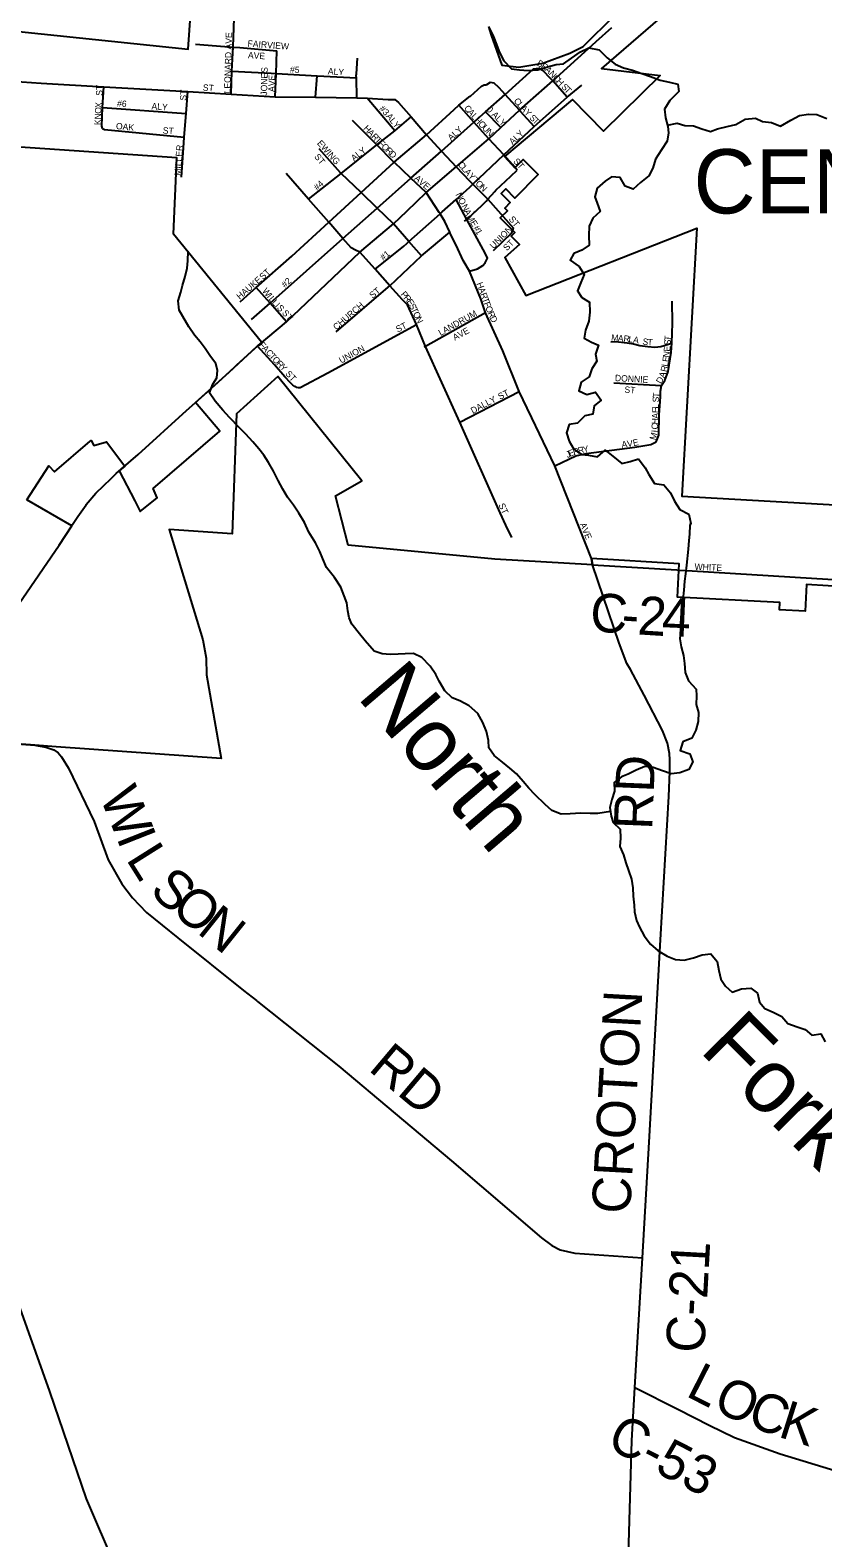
# Model space of a CAD drawing. Extents: x 1759416 to 2214760, y 252598 to 1116833.
# Drawn here: x 1910678 to 1916849, y 828969 to 840708 of the extents above; entities that cross this region are included whole.
import ezdxf

# ---------------------------------------------------------------- set-up
doc = ezdxf.new("R2010")
doc.units = 0
for name, color, linetype in [('GM_X_City_Street', 7, 'Continuous'), ('GM_X_City_Street_Text', 7, 'Continuous'), ('GM_X_Corporation', 7, 'Continuous'), ('GM_X_Corporation_Text', 7, 'Continuous'), ('GM_X_County_Road', 7, 'Continuous'), ('GM_X_County_Road_Text', 7, 'Continuous'), ('GM_X_Major_River', 7, 'Continuous'), ('GM_X_Major_River_Text', 7, 'Continuous'), ('GM_X_Minor_River', 7, 'Continuous'), ('GM_X_Township_Road', 7, 'Continuous'), ('GM_X_Township_Road_Text', 7, 'Continuous'), ('GM_X_US_Route', 7, 'Continuous')]:
    doc.layers.add(name, color=color, linetype=linetype)

msp = doc.modelspace()

# ---------------------------------------------------------------- linework, layer by layer
at = {"layer": 'GM_X_City_Street'}
for points in [[(1912257, 840579), (1912269, 840873), (1912279, 841107)], [(1911964, 840600), (1912257, 840576), (1912310, 840572)], [(1912242, 840210), (1912249, 840390), (1912257, 840576), (1912257, 840579)], [(1912310, 840572), (1912310, 840572), (1912599, 840548)], [(1912592, 840369), (1912592, 840371), (1912599, 840548)], [(1913218, 840367), (1913226, 840491)], [(1909520, 840374), (1909783, 840362), (1910763, 840296), (1911251, 840268), (1911905, 840230), (1912242, 840210), (1912585, 840190), (1912898, 840186), (1913222, 840182), (1913301, 840179), (1913465, 840169), (1913516, 840167), (1913546, 840146), (1913643, 840033), (1913762, 839892), (1913879, 839767), (1913993, 839645)], [(1912249, 840390), (1912555, 840373), (1912555, 840373)], [(1912400, 838454), (1912545, 838583), (1913111, 839086), (1913379, 839323), (1913642, 839556), (1913879, 839767), (1914132, 839992), (1914222, 840072), (1914375, 840208), (1914596, 840406), (1914637, 840412)], [(1912555, 840373), (1912592, 840371), (1912913, 840353), (1913218, 840336)], [(1912585, 840190), (1912592, 840369)], [(1914731, 840329), (1914670, 840393), (1914637, 840412)], [(1911241, 839942), (1911235, 839961), (1911242, 840105), (1911251, 840268)], [(1912898, 840186), (1912913, 840353)], [(1913222, 840182), (1913218, 840336), (1913217, 840356), (1913218, 840367)], [(1914103, 840193), (1914105, 840194), (1914192, 840273), (1914212, 840283), (1914230, 840282)], [(1914355, 840230), (1914326, 840261), (1914290, 840296), (1914259, 840300), (1914230, 840282)], [(1914859, 840187), (1914746, 840313), (1914731, 840329)], [(1914859, 840187), (1914973, 840279)], [(1911875, 839830), (1911878, 839876), (1911892, 840060), (1911905, 840230)], [(1913517, 839924), (1913301, 840179)], [(1913979, 840091), (1914014, 840123), (1914103, 840193)], [(1914121, 839506), (1914124, 839508), (1914366, 839736), (1914601, 839957), (1914859, 840187)], [(1914496, 840075), (1914486, 840086), (1914375, 840208), (1914355, 840230)], [(1911242, 840105), (1911892, 840060)], [(1912392, 838665), (1912437, 838705), (1912715, 838949), (1913002, 839212), (1913254, 839443), (1913512, 839679), (1913762, 839892), (1913979, 840091)], [(1912845, 839393), (1913098, 839593), (1913377, 839814), (1913517, 839924), (1913643, 840033)], [(1914470, 839619), (1914434, 839663), (1914366, 839736), (1914248, 839863), (1914132, 839992), (1914014, 840123)], [(1914341, 839950), (1914222, 840072)], [(1914601, 839957), (1914496, 840075)], [(1911241, 839942), (1911256, 839934), (1911878, 839876)], [(1913505, 839686), (1913377, 839814), (1913186, 840005)], [(1911855, 839563), (1911875, 839830), (1911875, 839830)], [(1913095, 839597), (1912927, 839783)], [(1913760, 839445), (1913642, 839556), (1913512, 839679), (1913505, 839686)], [(1913210, 838995), (1913176, 839012), (1913111, 839086), (1913002, 839212), (1912845, 839393), (1912671, 839593)], [(1913725, 838950), (1913626, 839063), (1913507, 839200), (1913379, 839323), (1913254, 839443), (1913098, 839593), (1913095, 839597)], [(1913993, 839645), (1914097, 839535)], [(1914304, 839461), (1914421, 839570), (1914470, 839619)], [(1913951, 839120), (1913944, 839134), (1913906, 839218), (1913869, 839279), (1913863, 839288), (1913760, 839445)], [(1913885, 839294), (1913993, 839390), (1914100, 839485), (1914121, 839506)], [(1914097, 839535), (1914105, 839527), (1914124, 839508), (1914205, 839429)], [(1914205, 839429), (1914242, 839393), (1914441, 839167)], [(1914227, 839376), (1914242, 839393), (1914296, 839453), (1914304, 839461)], [(1914098, 838831), (1914159, 838851), (1914203, 838876), (1914221, 838897), (1914239, 838934), (1914219, 838972), (1914076, 839235), (1913993, 839390)], [(1914144, 839297), (1914208, 839356), (1914227, 839376)], [(1913609, 839048), (1913626, 839063), (1913869, 839279), (1913885, 839294)], [(1914060, 839220), (1914076, 839235), (1914134, 839288), (1914144, 839297)], [(1913465, 838706), (1913478, 838717), (1913725, 838950), (1913944, 839134)], [(1914584, 837690), (1914548, 837765), (1914484, 837894), (1914358, 838211), (1914223, 838508), (1914185, 838617), (1914098, 838831), (1914050, 838914), (1913993, 839034), (1913951, 839120)], [(1914286, 838993), (1914427, 839131), (1914441, 839167)], [(1914011, 837684), (1913755, 838246), (1913686, 838417), (1913615, 838570), (1913577, 838608), (1913478, 838717), (1913363, 838848), (1913244, 838979), (1913210, 838995)], [(1913363, 838848), (1913586, 839027), (1913609, 839048)], [(1912312, 838594), (1912392, 838665)], [(1912673, 838437), (1912545, 838583), (1912437, 838705)], [(1913059, 838358), (1913465, 838706)], [(1914223, 838508), (1913755, 838246), (1913745, 838240)], [(1915593, 837941), (1915619, 837981), (1915645, 838050), (1915669, 838198), (1915672, 838270), (1915679, 838426), (1915675, 838598)], [(1912748, 837928), (1912765, 837925), (1912780, 837927), (1912994, 838040), (1913686, 838417)], [(1915197, 838282), (1915235, 838283), (1915325, 838274), (1915375, 838267), (1915424, 838252), (1915486, 838244), (1915542, 838240), (1915588, 838246), (1915672, 838270)], [(1912748, 837928), (1912737, 837933), (1912724, 837943), (1912705, 837963), (1912661, 838008), (1912580, 838102), (1912447, 838248)], [(1915221, 837962), (1915593, 837941)], [(1915550, 837504), (1915571, 837555), (1915575, 837714), (1915584, 837853), (1915585, 837896), (1915593, 837941)], [(1914023, 837657), (1914484, 837894)], [(1914338, 836951), (1914023, 837657), (1914011, 837684)], [(1915055, 836544), (1915048, 836595), (1914762, 837317), (1914584, 837690)], [(1914762, 837317), (1914925, 837393), (1915005, 837411), (1915385, 837460), (1915509, 837483), (1915550, 837504)], [(1914427, 836757), (1914381, 836854), (1914338, 836951)], [(1915731, 836504), (1915832, 836498), (1917226, 836412), (1917240, 836411)]]:
    msp.add_lwpolyline(points, dxfattribs=at)
at = {"layer": 'GM_X_Corporation'}
for points in [[(1910464, 840711), (1911908, 840559), (1912003, 841929)], [(1916038, 841202), (1915126, 840409), (1915581, 840356), (1915142, 839922), (1914899, 840169), (1914370, 839724), (1914452, 839635), (1914517, 839700), (1914633, 839583), (1914451, 839401), (1914380, 839472), (1914345, 839437), (1914415, 839366), (1914373, 839323), (1914394, 839302), (1914337, 839246), (1914450, 839132), (1914422, 839104), (1914487, 839039), (1914373, 838938), (1914536, 838641), (1915869, 839166), (1915751, 837079), (1917264, 836994)], [(1914246, 840737), (1914267, 840669), (1914350, 840436), (1914482, 840419), (1914669, 840451), (1914880, 840528), (1914982, 840580), (1915229, 840824)], [(1910652, 837052), (1910822, 837317), (1910867, 837270), (1911144, 837507), (1911153, 837512), (1911173, 837473), (1911273, 837504), (1911415, 837314), (1911372, 837277), (1911492, 837043), (1911533, 836961), (1911666, 837067), (1911635, 837139), (1912154, 837585), (1911965, 837808), (1912227, 838046), (1912479, 838278), (1911793, 839120), (1911820, 839713), (1910333, 839814)], [(1917228, 836362), (1916722, 836393), (1916712, 836184), (1916512, 836195), (1916515, 836252), (1915716, 836294), (1915730, 836554), (1915048, 836595), (1915055, 836544), (1914295, 836590), (1913153, 836697), (1913054, 837082), (1913261, 837198), (1912607, 838012), (1912284, 837720), (1912251, 836787), (1911759, 836821), (1912022, 835962), (1912047, 835818), (1912050, 835689), (1912164, 835037), (1910881, 835127), (1910714, 835140), (1910611, 835150)], [(1910621, 836286), (1910904, 836697), (1911001, 836848), (1910652, 837052)]]:
    msp.add_lwpolyline(points, dxfattribs=at)
at = {"layer": 'GM_X_County_Road'}
for points in [[(1915272, 828533), (1915299, 828607), (1915314, 828656), (1915319, 828724), (1915335, 828838), (1915361, 829727), (1915385, 830140), (1915419, 830710), (1915444, 831150), (1915496, 832049), (1915584, 833625), (1915649, 834741), (1915657, 834937), (1915658, 835027), (1915654, 835077), (1915639, 835157), (1915600, 835256), (1915457, 835530), (1915351, 835731), (1915323, 835777), (1915263, 835934), (1915055, 836544)], [(1915055, 836544), (1915713, 836505), (1915731, 836504)], [(1915385, 830140), (1915724, 829968), (1915965, 829847), (1916162, 829751), (1916516, 829624), (1916969, 829485), (1917203, 829435), (1917350, 829400), (1917440, 829373), (1917542, 829330), (1917705, 829256), (1918107, 829050), (1918465, 828869), (1918726, 828709), (1918986, 828539), (1919156, 828428), (1919288, 828347), (1919327, 828329), (1919359, 828320), (1919435, 828299)]]:
    msp.add_lwpolyline(points, dxfattribs=at)
at = {"layer": 'GM_X_Major_River'}
for points in [[(1914250, 840726), (1914285, 840655), (1914309, 840597), (1914331, 840535), (1914364, 840469), (1914424, 840408), (1914487, 840398), (1914555, 840393), (1914631, 840399), (1914705, 840423), (1914773, 840440), (1914829, 840446), (1914893, 840491), (1914962, 840539), (1915028, 840571), (1915108, 840556), (1915169, 840492), (1915231, 840443), (1915298, 840415), (1915368, 840396), (1915440, 840370), (1915508, 840347), (1915581, 840319), (1915655, 840304), (1915721, 840288), (1915727, 840230), (1915658, 840160), (1915616, 840093), (1915623, 840026), (1915641, 839958), (1915647, 839908), (1915636, 839844), (1915592, 839776), (1915545, 839703), (1915525, 839633), (1915493, 839575), (1915428, 839523), (1915372, 839470), (1915310, 839494), (1915271, 839562), (1915203, 839565), (1915153, 839531), (1915091, 839479), (1915074, 839411), (1915092, 839361), (1915115, 839295), (1915059, 839245), (1915029, 839181), (1915028, 839109), (1915030, 839035), (1914973, 838994), (1914909, 838970), (1914881, 838916), (1914953, 838868), (1914990, 838805), (1914966, 838743), (1914939, 838678), (1914973, 838627), (1915033, 838589), (1915036, 838513), (1915026, 838443), (1915001, 838373), (1914991, 838309), (1915049, 838279), (1915102, 838256), (1915080, 838186), (1915090, 838130), (1915051, 838072), (1915029, 838008), (1914967, 837967), (1914950, 837899), (1915012, 837872), (1915078, 837890), (1915123, 837828), (1915069, 837784), (1915059, 837718), (1914995, 837706), (1914939, 837649), (1914873, 837639), (1914854, 837573), (1914874, 837507), (1914909, 837445), (1914973, 837404), (1915025, 837398), (1915095, 837386), (1915155, 837437), (1915214, 837391), (1915284, 837334), (1915348, 837350), (1915414, 837370)], [(1915414, 837370), (1915466, 837301), (1915495, 837249), (1915539, 837179), (1915612, 837168), (1915664, 837106), (1915693, 837040), (1915735, 836977), (1915805, 836939), (1915822, 836867)], [(1915822, 836867), (1915812, 836853), (1915810, 836785), (1915805, 836735), (1915801, 836667), (1915788, 836543), (1915780, 836475), (1915773, 836417), (1915767, 836347), (1915758, 836275), (1915748, 836197), (1915743, 836134), (1915741, 836082), (1915741, 836032), (1915736, 835970), (1915746, 835906), (1915765, 835838), (1915773, 835776), (1915776, 835708), (1915802, 835642), (1915863, 835577), (1915865, 835525), (1915863, 835457), (1915880, 835395), (1915878, 835325), (1915861, 835257), (1915829, 835195), (1915759, 835166), (1915738, 835100), (1915812, 835073), (1915836, 835011), (1915805, 834951), (1915735, 834926), (1915667, 834918), (1915600, 834942), (1915528, 834967), (1915464, 834975), (1915396, 834946), (1915332, 834914), (1915280, 834894), (1915225, 834851), (1915227, 834783), (1915205, 834719), (1915190, 834655), (1915200, 834589), (1915217, 834539), (1915271, 834488), (1915273, 834418), (1915268, 834352), (1915298, 834288), (1915315, 834226), (1915337, 834164), (1915358, 834097), (1915370, 834031), (1915371, 833965), (1915379, 833895), (1915383, 833843), (1915398, 833775), (1915422, 833723), (1915457, 833656), (1915507, 833592), (1915566, 833540), (1915638, 833499), (1915702, 833473), (1915769, 833466), (1915841, 833484), (1915908, 833509), (1915977, 833517), (1916025, 833457), (1916040, 833387), (1916054, 833318), (1916090, 833264), (1916143, 833218), (1916215, 833243), (1916287, 833249), (1916339, 833209), (1916356, 833140), (1916398, 833090), (1916462, 833062), (1916529, 833029), (1916577, 832975), (1916649, 832948), (1916710, 832928), (1916764, 832882), (1916832, 832893), (1916868, 832831)]]:
    msp.add_lwpolyline(points, dxfattribs=at)
at = {"layer": 'GM_X_Minor_River'}
for points in [[(1915639, 839967), (1915715, 839983), (1915775, 839965), (1915843, 839963), (1915907, 839941), (1915975, 839919), (1916029, 839941), (1916103, 839957), (1916172, 839974), (1916244, 840014), (1916324, 840024), (1916378, 839996), (1916448, 839990), (1916520, 839960), (1916600, 840008), (1916668, 840044), (1916737, 840053), (1916803, 840051), (1916879, 840019)], [(1915195, 834624), (1915098, 834609), (1915038, 834609), (1914966, 834612), (1914882, 834606), (1914812, 834604), (1914739, 834632), (1914687, 834680), (1914607, 834757), (1914559, 834807), (1914516, 834859), (1914464, 834917), (1914412, 834963), (1914354, 835010), (1914291, 835060), (1914249, 835120), (1914245, 835178), (1914231, 835248), (1914203, 835318), (1914164, 835387), (1914096, 835447), (1914022, 835485), (1913962, 835509), (1913905, 835563), (1913861, 835640), (1913837, 835690), (1913793, 835756), (1913726, 835824), (1913662, 835854), (1913598, 835853), (1913542, 835849), (1913480, 835847), (1913419, 835851), (1913357, 835873), (1913285, 835953), (1913241, 836008), (1913182, 836082), (1913162, 836132), (1913152, 836186), (1913142, 836248), (1913122, 836304), (1913096, 836371), (1913047, 836447), (1912985, 836525), (1912957, 836591), (1912933, 836649), (1912900, 836716), (1912848, 836800), (1912814, 836876), (1912769, 836948), (1912727, 837010), (1912681, 837071), (1912645, 837135), (1912608, 837201), (1912572, 837275), (1912534, 837341), (1912496, 837398), (1912458, 837448), (1912411, 837502), (1912357, 837562), (1912307, 837612), (1912230, 837693), (1912178, 837749), (1912118, 837819), (1912074, 837883), (1912100, 837951), (1912130, 838002), (1912137, 838058), (1912123, 838112), (1912083, 838168), (1912041, 838230), (1912001, 838282), (1911956, 838332), (1911912, 838399), (1911866, 838479), (1911838, 838529), (1911831, 838601), (1911851, 838667), (1911865, 838721), (1911885, 838791), (1911899, 838856), (1911905, 838912), (1911909, 838988)]]:
    msp.add_lwpolyline(points, dxfattribs=at)
at = {"layer": 'GM_X_Township_Road'}
for points in [[(1909086, 835267), (1909095, 835037), (1909109, 834371), (1909097, 833891), (1909105, 833452), (1909113, 833302), (1909123, 833241), (1909146, 833159), (1909279, 832843), (1909330, 832747), (1909381, 832666), (1909456, 832585), (1909629, 832429), (1910061, 832004), (1910162, 831901), (1910195, 831861), (1910235, 831800), (1910311, 831581), (1910544, 830910), (1910828, 830108), (1911114, 829274), (1911341, 828740)], [(1910264, 835173), (1910611, 835150), (1910714, 835140), (1910739, 835136)], [(1910739, 835136), (1910801, 835126), (1910861, 835106), (1910895, 835081), (1910922, 835051), (1910977, 834962), (1911175, 834546), (1911285, 834247), (1911392, 834061), (1911474, 833952), (1911583, 833837), (1911827, 833641), (1912339, 833231), (1912440, 833152)], [(1912440, 833152), (1912447, 833146), (1913082, 832643), (1913959, 831906), (1914659, 831304), (1914740, 831245), (1914804, 831213), (1914918, 831187), (1915444, 831150)]]:
    msp.add_lwpolyline(points, dxfattribs=at)
at = {"layer": 'GM_X_US_Route'}
for points in [[(1915085, 840620), (1915206, 840729)], [(1913993, 839645), (1914248, 839863), (1914341, 839950), (1914486, 840086), (1914746, 840313), (1915052, 840590), (1915085, 840620)], [(1913609, 839299), (1913760, 839445), (1913993, 839645)], [(1912401, 838205), (1912447, 838248), (1912673, 838437), (1913244, 838979), (1913507, 839200), (1913609, 839299)], [(1912285, 838099), (1912401, 838205)], [(1912169, 837993), (1912272, 838087), (1912285, 838099)], [(1911896, 837746), (1912032, 837869), (1912169, 837993)], [(1911387, 837290), (1911519, 837404), (1911896, 837746)], [(1911007, 836858), (1911048, 836922), (1911113, 837012), (1911115, 837014), (1911188, 837102), (1911249, 837161), (1911308, 837217), (1911348, 837255)], [(1911348, 837255), (1911368, 837274), (1911387, 837290)], [(1910174, 835645), (1910621, 836286), (1910904, 836697), (1911001, 836848), (1911007, 836858)]]:
    msp.add_lwpolyline(points, dxfattribs=at)

# ---------------------------------------------------------------- texts
at = {"layer": 'GM_X_City_Street_Text'}
for s, rotation, p in [('LEONARD AVE', 88.2475, (1912236, 840215)), ('FAIRVIEW', 355.797, (1912369, 840580)), ('AVE', 356.0569, (1912372, 840490)), ('JONES', 88.6036, (1912522, 840197)), ('#5', 355.9166, (1912699, 840378)), ('ALY', 356.0569, (1912994, 840365)), ('B', 328.0409, (1914617, 840438)), ('R', 323.8101, (1914650, 840418)), ('A', 315.1082, (1914681, 840396)), ('N', 313.7174, (1914712, 840365)), ('ST', 90, (1911241, 840197)), ('ST', 356.4262, (1912021, 840237)), ('AVE', 88.0261, (1912581, 840226)), ('C', 313.7114, (1914742, 840333)), ('H', 313.7252, (1914769, 840304)), ('S', 313.7055, (1914809, 840263)), ('T', 313.7146, (1914833, 840238)), ('X', 85.2291, (1911233, 840100)), ('#6', 355.9166, (1911353, 840114)), ('ALY', 356.0569, (1911621, 840092)), ('ST', 86.4118, (1911893, 840158)), ('C', 310.6856, (1914439, 840155)), ('L', 311.0383, (1914465, 840124)), ('N', 88.12, (1911230, 840012)), ('O', 87.726, (1911231, 840056)), ('#3', 311.9884, (1913392, 840093)), ('ALY', 309.2818, (1913445, 840036)), ('C', 311.0306, (1914052, 840098)), ('A', 311.034, (1914078, 840068)), ('L', 311.1083, (1914107, 840034)), ('H', 312.9133, (1914131, 840007)), ('0 ALY', 315, (1914227, 840085)), ('A', 313.2158, (1914490, 840096)), ('Y', 313.948, (1914520, 840064)), ('S', 313.957, (1914560, 840022)), ('T', 313.9454, (1914585, 839997)), ('K', 88.12, (1911228, 839968)), ('OAK', 354.2923, (1911344, 839938)), ('ST', 356.4254, (1911709, 839903)), ('H', 313.9337, (1913268, 839939)), ('A', 313.9321, (1913299, 839908)), ('R', 313.947, (1913330, 839876)), ('ALY', 42.2752, (1913955, 839843)), ('O', 313.9321, (1914162, 839974)), ('U', 313.964, (1914192, 839942)), ('N', 313.964, (1914223, 839910)), ('ALY', 43.6036, (1914434, 839812)), ('MILLER', 85.5994, (1911849, 839573)), ('EWING', 311.5338, (1912908, 839825)), ('ALY', 38.0509, (1913199, 839685)), ('T', 314.3011, (1913357, 839847)), ('F', 315.6153, (1913383, 839821)), ('O', 316.0504, (1913408, 839796)), ('R', 316.1134, (1913440, 839766)), ('ST', 309.7984, (1912886, 839721)), ('D', 316.0821, (1913468, 839738)), ('C', 311.8049, (1914004, 839658)), ('ST', 312.5121, (1914435, 839684)), ('AVE', 319.1826, (1913664, 839548)), ('L', 311.7892, (1914030, 839628)), ('A', 311.7988, (1914053, 839602)), ('Y', 312.4198, (1914083, 839569)), ('T', 315.4551, (1914115, 839534)), ('#4', 41.9884, (1912912, 839456)), ('N', 297.1223, (1913987, 839427)), ('O', 316.3056, (1914140, 839509)), ('N', 316.3374, (1914172, 839478)), ('O', 297.1223, (1914007, 839388)), ('N', 297.1141, (1914033, 839337)), ('A', 297.1141, (1914053, 839298)), ('M', 298.9943, (1914074, 839257)), ('E', 300.3331, (1914101, 839210)), ('ST', 309.8074, (1914400, 839235)), ('#', 300.3801, (1914125, 839168)), ('1', 300.3828, (1914141, 839141)), ('UNION', 45, (1914285, 839002)), ('ST', 45, (1914389, 838986)), ('#1', 39.2916, (1913427, 838911)), ('ST', 42.5022, (1912490, 838761)), ('HAUKE', 40.8528, (1912310, 838607)), ('#2', 41.9884, (1912661, 838699)), ('H', 290.4537, (1914151, 838735)), ('W', 308.7228, (1912481, 838676)), ('I', 308.738, (1912517, 838631)), ('L', 309.7638, (1912532, 838613)), ('L', 312.6103, (1912556, 838584)), ('ST', 39.8092, (1913344, 838616)), ('P', 309.2529, (1913559, 838650)), ('R', 309.279, (1913582, 838622)), ('E', 304.175, (1913606, 838593)), ('A', 290.4734, (1914166, 838694)), ('R', 290.4395, (1914181, 838653)), ('T', 290.4646, (1914195, 838615)), ('I', 313.2279, (1912580, 838558)), ('S', 313.269, (1912595, 838542)), ('ST', 309.8181, (1912635, 838505)), ('CHURCH', 40.8146, (1913062, 838369)), ('S', 296.6995, (1913625, 838565)), ('T', 295.38, (1913641, 838534)), ('O', 295.3628, (1913656, 838502)), ('LANDRUM', 29.1315, (1913873, 838326)), ('F', 290.4569, (1914207, 838582)), ('O', 291.4728, (1914220, 838549)), ('R', 294.834, (1914237, 838505)), ('ST', 26.565, (1913539, 838353)), ('N', 296.3486, (1913675, 838462)), ('AVE', 28.2997, (1913984, 838290)), ('D', 295.4671, (1914254, 838468)), ('F', 312.2939, (1912455, 838254)), ('UNION', 28.8095, (1913099, 838111)), ('M', 354.2532, (1915199, 838292)), ('A', 354.2703, (1915251, 838287)), ('R', 354.2661, (1915295, 838283)), ('L', 353.7322, (1915334, 838279)), ('A', 350.8683, (1915369, 838275)), ('S', 350.8072, (1915442, 838261)), ('T', 356.2658, (1915482, 838255)), ('S', 86.1773, (1915663, 838253)), ('T', 86.2021, (1915665, 838288)), ('A', 312.2943, (1912478, 838228)), ('C', 312.2996, (1912508, 838195)), ('T', 312.3073, (1912535, 838166)), ('O', 312.77, (1912559, 838140)), ('R', 314.602, (1912590, 838106)), ('E', 81.7331, (1915648, 838122)), ('N', 82.3499, (1915653, 838157)), ('E', 85.4303, (1915659, 838204)), ('Y', 314.9833, (1912618, 838078)), ('ST', 312.5121, (1912661, 838030)), ('DONNIE', 356.7622, (1915229, 837976)), ('A', 69.7842, (1915616, 837996)), ('R', 77.5651, (1915633, 838044)), ('L', 81.1534, (1915642, 838086)), ('ST', 26.565, (1914335, 837829)), ('ST', 356.4254, (1915303, 837885)), ('D', 60.697, (1915590, 837950)), ('DALLY', 28.2164, (1914124, 837719)), ('L', 87.5048, (1915571, 837761)), ('S', 87.5128, (1915573, 837809)), ('T', 89.1911, (1915575, 837846)), ('H', 87.4933, (1915566, 837638)), ('A', 87.5158, (1915568, 837682)), ('E', 87.4855, (1915570, 837726)), ('M', 73.5467, (1915546, 837513)), ('I', 86.4149, (1915563, 837575)), ('C', 87.3319, (1915564, 837598)), ('J', 22.946, (1914860, 837376)), ('E', 22.3697, (1914880, 837385)), ('R', 16.3991, (1914911, 837398)), ('R', 12.7343, (1914948, 837409)), ('Y', 12.5146, (1914987, 837417)), ('A', 7.8272, (1915285, 837456)), ('V', 7.8265, (1915328, 837462)), ('E', 11.3683, (1915375, 837469)), ('ST', 295.0177, (1914322, 837011)), ('AVE', 292.1689, (1914956, 836861)), ('WHITE', 357.4565, (1915849, 836506))]:
    msp.add_text(s, height=50, rotation=rotation, dxfattribs=at).set_placement(p)
at = {"layer": 'GM_X_Corporation_Text'}
msp.add_text('CENTERBURG', height=500, rotation=0, dxfattribs=at).set_placement((1915842, 839281))
at = {"layer": 'GM_X_County_Road_Text'}
for s, rotation, p in [('C', 356.1135, (1915030, 836029)), ('2', 356.3719, (1915401, 836004)), ('4', 357.53, (1915592, 835992)), ('-', 356.1607, (1915276, 836013)), ('RD', 87.6163, (1915520, 834479)), ('CROTON', 86.8292, (1915348, 831487)), ('C-21', 86.8959, (1915925, 830404)), ('L', 333.0286, (1915773, 830078)), ('O', 334.7047, (1915981, 829972)), ('C', 339.9377, (1916248, 829848)), ('K', 342.4066, (1916492, 829759)), ('C-53', 332.9893, (1915153, 829679))]:
    msp.add_text(s, height=300, rotation=rotation, dxfattribs=at).set_placement(p)
at = {"layer": 'GM_X_Major_River_Text'}
for s, rotation, p in [('North', 310.4648, (1913215, 835517)), ('Fork', 314.8493, (1915880, 832761))]:
    msp.add_text(s, height=500, rotation=rotation, dxfattribs=at).set_placement(p)
at = {"layer": 'GM_X_Township_Road_Text'}
for s, rotation, p in [('W', 292.2278, (1911216, 834744)), ('I', 291.5318, (1911347, 834423)), ('L', 302.1727, (1911420, 834254)), ('S', 318.0999, (1911598, 833995)), ('O', 321.2494, (1911763, 833848)), ('N', 321.2948, (1911969, 833683)), ('RD', 319.8792, (1913303, 832614))]:
    msp.add_text(s, height=300, rotation=rotation, dxfattribs=at).set_placement(p)

doc.saveas('drawing.dxf')
